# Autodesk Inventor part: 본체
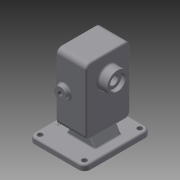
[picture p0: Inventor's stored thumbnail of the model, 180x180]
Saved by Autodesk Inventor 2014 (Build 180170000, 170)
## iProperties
Created: 2020-04
Part Number: 본체
Material: Generic
Document SubType Name: Modeling
Designer: kh
Density: 1 g/cm^3
Appearance: Default
Mass: 544.812 g
Surface Area: 819.925 cm^2
Volume: 544.812 cm^3
Author: kh
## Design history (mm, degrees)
sketch "스케치1"
  geometry: L1 (-50, -60)-(50, -60); L2 (50, -60)-(50, 60); L3 (50, 60)-(-50, 60); L4 (-50, 60)-(-50, -60); L5 (-50, -60)-(50, 60); L6 (50, -60)-(-50, 60); 1 further point
  constraints: 12 end point, 2 midpoint, 2 parallel, 1 horizontal, 1 perpendicular
  dimensions: "d0" = 100 distance of L3.end L2.end; "d1" = 120 distance of L2.end L1.end
extrude "돌출1" new body sketch "스케치1" distance "d2" = 10; taper "d3" = 0 deg
node "작업 평면1"
sketch "스케치2"
  geometry: L1 (0, 60)-(90, 60); L2 (30, 100)-(150, 100); L3 (150, 100)-(150, 20); L4 (150, 20)-(30, 20); L5 (30, 20)-(30, 100); L6 (30, 100)-(150, 20); L7 (150, 100)-(30, 20)
  constraints: 14 end point, 2 horizontal, 2 midpoint, 2 parallel, 1 perpendicular
  dimensions: "d5" = 90 distance of L1.start L1.end; "d6" = 80 distance of L2.end L3.end; "d7" = 120 distance of L3.end L4.end
extrude "돌출2" join sketch "스케치2" distance "d8" = 53; taper "d9" = 0 deg
sketch "스케치3"
  geometry: L1 (0, 60)-(-112, 60); C1 r 19 at (-112, 60)
  constraints: 2 end point, 1 centre point, 1 coincident, 1 horizontal
  dimensions: "d10" = 112 distance of L1.start L1.end; "d11" = 38 diameter of C1
extrude "돌출3" join sketch "스케치3" distance "d12" = 17; taper "d13" = 0 deg
sketch "스케치4"
  geometry: L1 (30, 100)-(150, 100) reference; L2 (30, 20)-(30, 100) reference; L3 (150, 20)-(30, 20) reference; L4 (150, 100)-(150, 20) reference; L5 (0, 60)-(150, 60); L6 (112, 60)-(68, 60); L7 (112, 84)-(68, 84); L8 (68, 36)-(112, 36); L9 (112, 100)-(112, 20); L10 (0, 0)-(0, 120) reference; A1 r 24 centre (112, 60) between (112, 36) and (112, 84); A2 r 24 centre (68, 60) between (68, 84) and (68, 36); 1 further point
  constraints: 12 end point, 4 point on circle, 4 point on line, 4 tangent, 3 midpoint, 2 centre point, 1 parallel, 1 perpendicular
  dimensions: "d14" = 92 dimension on A2 A1; "d15" = 112 distance between parallel lines of L9 L10; "d16" = 24 radius of A1
extrude "돌출4" cut sketch "스케치4" distance "d17" = 29; taper "d18" = 0 deg
sketch "스케치5"
  geometry: L1 (-50, 131)-(-50, 93) reference; L2 (20, 30)-(20, 150) reference; L3 (-50, 112)-(-9, 112); L4 (-9, 136)-(-9, 112) reference; L5 (-9, 124.5)-(-24, 124.5); L6 (-24, 124.5)-(-24, 120.5); L7 (-24, 120.5)-(-42.7, 120.5); L8 (-42.7, 120.5)-(-42.7, 126); L9 (-42.7, 126)-(-50, 126); L10 (-9, 124.5)-(-9, 112); L11 (-50, 126)-(-50, 112); 1 further point
  constraints: 16 end point, 5 perpendicular, 3 point on line, 2 parallel, 1 collinear, 1 midpoint
  dimensions: "d19" = 25 diameter of L5 L3; "d20" = 17 diameter of L7 L3; "d21" = 28 diameter of L9 L3; "d22" = 15 distance of L5.start L5.end; "d23" = 7.3 distance of L8.end L9.end
revolve "회전1" sketch "스케치5" stored, may be unused: angle "d24" = 90 deg
sketch "스케치6"
  geometry: L1 (-9, 68)-(-9, 44) reference; L2 (-9, 68)-(-9, 112) reference; L3 (-33, 30)-(-33, 150) reference; L4 (-50, 98)-(-50, 126) reference; L5 (-9, 112)-(-50, 112); L6 (-9, 68)-(-33, 68); L7 (-9, 68)-(-9, 80.5); L8 (-24, 80.5)-(-24, 68); L9 (-9, 80.5)-(-24, 80.5); 1 further point
  constraints: 10 end point, 4 point on line, 3 perpendicular, 1 midpoint
  dimensions: "d25" = 44 distance between parallel lines of L6 L5; "d26" = 25 diameter of L9 L6; "d27" = 15 distance of L7.end L8.start
revolve "회전2" sketch "스케치6" stored, may be unused: angle "d28" = 90 deg
sketch "스케치7"
  geometry: L1 (0, 120)-(53, 120) reference; L2 (0, 0)-(53, 0) reference; L3 (14, 120)-(14, 0); L4 (0, 120)-(0, 0) reference; L5 (53, 120)-(53, 0) reference; L6 (0, 60)-(53, 60); L7 (-30, -30)-(70, -30) reference; C1 r 11 at (14, 60); 1 further point
  constraints: 4 end point, 3 midpoint, 3 point on line, 2 perpendicular, 1 centre point
  dimensions: "d29" = 14 distance between parallel lines of L3 L4; "d30" = 90 distance between parallel lines of L6 L7; "d31" = 22 diameter of C1
extrude "돌출5" join sketch "스케치7" distance "d32" = 8; taper "d33" = 0 deg
hole "구멍1" diameter "d36" = 8.917; stored, may be unused: countersink angle "d40" = 90 deg, drill point angle "d42" = 118 deg; dims "d34" = 10, "d35" = 10, "d37" = 6, "d38" = 4, "d39" = 2, "d41" = 8
sketch "스케치8"
  geometry: L1 (150, 20)-(30, 20) reference; L2 (30, 100)-(150, 100) reference; L3 (150, 100)-(150, 20) reference; L4 (30, 20)-(30, 100) reference; L5 (90, 100)-(90, 20); L6 (150, 60)-(30, 60); L7 (39, 91)-(141, 91); L8 (141, 91)-(141, 29); L9 (141, 29)-(39, 29); L10 (39, 29)-(39, 91); L11 (39, 91)-(141, 29); L12 (141, 91)-(39, 29); L13 (68, 91)-(68, 29); L14 (112, 91)-(112, 29); A1 r 24 centre (112, 60) between (112, 36) and (112, 84) reference; A2 r 24 centre (68, 60) between (68, 84) and (68, 36) reference; 10 further points
  constraints: 20 end point, 8 coincident, 7 midpoint, 4 point on line, 3 perpendicular, 2 parallel, 1 horizontal
  dimensions: "d43" = 102 distance of L8.end L9.end; "d44" = 62 distance of L7.end L8.end; "d45" = 22 distance between parallel lines of L14 L5; "d46" = 22 distance between parallel lines of L13 L5
hole "구멍2" sketch "스케치8" at (141, 91), (141, 29), (39, 91), (39, 29), (112, 91), (68, 91), (68, 29), (112, 29) diameter "d47" = 4.459; stored, may be unused: countersink angle "d51" = 90 deg, drill point angle "d53" = 118 deg; dims "d48" = 10, "d49" = 4, "d50" = 2, "d52" = 12
fillet "모깎기1" dims "d54" = 0.5
chamfer "모따기1" distance "d55" = 0.7; stored, may be unused: second distance "d56" = 2, angle "d57" = 30 deg
chamfer "모따기2" distance "d58" = 1; stored, may be unused: second distance "d59" = 2, angle "d60" = 30 deg
fillet "모깎기2" dims "d61" = 3, "d62" = 9
fillet "모깎기3" dims "d63" = 3
fillet "모깎기4" dims "d64" = 10
sketch "스케치9"
  geometry: A1 r 10 centre (-40, 50) between (-40, 60) and (-50, 50) reference; A2 r 10 centre (40, 50) between (50, 50) and (40, 60) reference; A3 r 10 centre (40, -50) between (40, -60) and (50, -50) reference; A4 r 10 centre (-40, -50) between (-50, -50) and (-40, -60) reference; 5 further points
  constraints: 4 coincident
hole "구멍3" sketch "스케치9" at (-40, 50), (40, 50), (40, -50), (-40, -50) diameter "d65" = 9; stored, may be unused: countersink angle "d69" = 90 deg, drill point angle "d71" = 118 deg; dims "d66" = 10, "d67" = 4, "d68" = 2, "d70" = 12
node "작업 평면2"
sketch "스케치10"
  geometry: L1 (70, 30)-(20, 30) reference; L2 (80, 10)-(0, 10) reference; L3 (20, 10)-(31.547, 30); L4 (73, 10)-(61.453, 30); L5 (90, 10)-(90, 0) reference; 1 further point
  constraints: 4 end point, 4 point on line
  dimensions: "d72" = 17 distance from line of L4.start L5; "d73" = 53 distance of L3.start L4.start; "d74" = 60 deg angle of L3 L2; "d75" = 60 deg angle of L2 L4
extrude "돌출6" join sketch "스케치10" stored distance "d76" = 48; taper "d77" = 0 deg
fillet "모깎기5" dims "d78" = 3
fillet "모깎기6" dims "d79" = 3
fillet "모깎기7" dims "d80" = 3
sketch "스케치11"
  geometry: L1 (-36.998, 20.739)-(-36.998, -20.739); L2 (-36.998, -20.739)-(-43.002, -20.739); L3 (-43.002, -20.739)-(-43.002, 20.739); L4 (-43.002, 20.739)-(-36.998, 20.739); L5 (-36.998, 20.739)-(-43.002, -20.739); L6 (-36.998, -20.739)-(-43.002, 20.739); L7 (-50, 50)-(-50, -50) reference; L8 (40, 60)-(-40, 60) reference; 2 further points
  constraints: 4 end point, 1 midpoint, 2 other
  dimensions: "d81" = 10 distance from line of point (-40, 0) L7; "d82" = 60 distance from line of point (-40, 0) L8
feature "엠보싱1" sketch "스케치11" dims "d0" = 100, "d1" = 120, "d83" = 0.5, "d84" = 0
node "솔리드1"
mirror "대칭1"
node "투영된 루프1"
